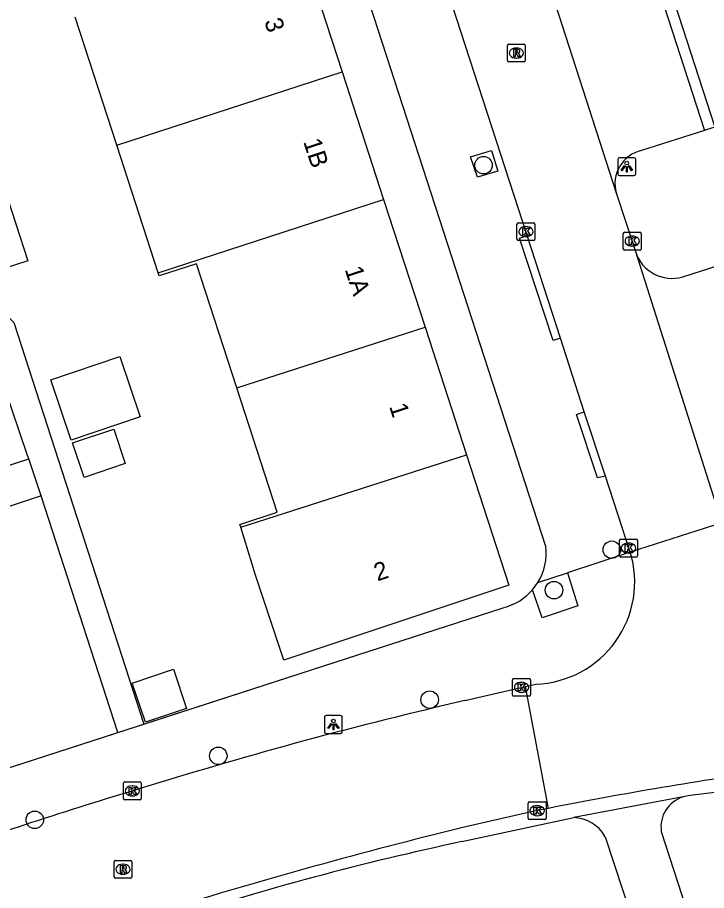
# Model space of a CAD drawing. Extents: x 159265 to 160143, y 383413 to 384319.
# Drawn here: x 159539.86 to 159578.35, y 383875.38 to 383924.16 of the extents above; entities that cross this region are included whole.
import ezdxf

# ---------------------------------------------------------------- set-up
doc = ezdxf.new("R2010")
doc.units = 0
for name, color, linetype in [('IMGEO_Boom', 7, 'Continuous'), ('IMGEO_Groenvoorziening', 7, 'Continuous'), ('IMGEO_Kolk', 7, 'Continuous'), ('IMGEO_Lichtpunt', 7, 'Continuous'), ('IMGEO_Muur', 7, 'Continuous'), ('IMGEO_Pand', 7, 'Continuous'), ('IMGEO_Pand_nummerreeks', 7, 'Continuous'), ('IMGEO_Parkeervlak_open', 7, 'Continuous'), ('IMGEO_Rijbaan_lokaal_open', 7, 'Continuous'), ('IMGEO_Rioolput', 7, 'Continuous'), ('IMGEO_Voetpad_open', 7, 'Continuous')]:
    doc.layers.add(name, color=color, linetype=linetype)

msp = doc.modelspace()

# ---------------------------------------------------------------- linework, layer by layer
at = {"layer": 'IMGEO_Boom'}
for centre in [(159565.896, 383915.907), (159573.059, 383894.421), (159569.835, 383892.161), (159562.889, 383886.043), (159551.075, 383882.908), (159540.823, 383879.332)]:
    msp.add_circle(centre, 0.489, dxfattribs=at)
at = {"layer": 'IMGEO_Groenvoorziening'}
msp.add_lwpolyline([(159568.639, 383892.186), (159568.936, 383892.591)], dxfattribs=at)
at = {"layer": 'IMGEO_Kolk'}
for p, q in [((159567.764, 383911.77), (159567.764, 383912.622)), ((159567.839, 383912.696), (159568.691, 383912.696)), ((159568.252, 383912.476), (159568.277, 383912.476)), ((159568.765, 383912.622), (159568.765, 383911.77)), ((159573.702, 383911.24), (159573.702, 383912.092)), ((159573.777, 383912.166), (159574.629, 383912.166)), ((159574.703, 383912.092), (159574.703, 383911.24)), ((159568.691, 383911.696), (159567.839, 383911.696)), ((159568.275, 383911.916), (159568.25, 383911.916)), ((159574.19, 383911.946), (159574.215, 383911.946)), ((159574.629, 383911.166), (159573.777, 383911.166)), ((159574.213, 383911.386), (159574.188, 383911.386)), ((159573.493, 383894.087), (159573.493, 383894.939)), ((159573.568, 383895.013), (159574.42, 383895.013)), ((159574.494, 383894.939), (159574.494, 383894.087)), ((159573.981, 383894.793), (159574.006, 383894.793)), ((159574.42, 383894.013), (159573.568, 383894.013)), ((159574.004, 383894.233), (159573.979, 383894.233)), ((159567.518, 383886.306), (159567.518, 383887.158)), ((159567.593, 383887.232), (159568.445, 383887.232)), ((159568.519, 383887.158), (159568.519, 383886.306)), ((159568.006, 383887.012), (159568.031, 383887.012)), ((159568.445, 383886.232), (159567.593, 383886.232)), ((159568.029, 383886.452), (159568.004, 383886.452)), ((159545.774, 383880.517), (159545.774, 383881.369)), ((159545.849, 383881.443), (159546.701, 383881.443)), ((159546.775, 383881.369), (159546.775, 383880.517)), ((159546.262, 383881.223), (159546.287, 383881.223)), ((159546.701, 383880.443), (159545.849, 383880.443)), ((159546.285, 383880.663), (159546.26, 383880.663)), ((159568.466, 383880.34), (159569.318, 383880.34)), ((159568.391, 383879.414), (159568.391, 383880.266)), ((159568.879, 383880.12), (159568.904, 383880.12)), ((159569.392, 383880.266), (159569.392, 383879.414)), ((159569.318, 383879.34), (159568.466, 383879.34)), ((159568.902, 383879.56), (159568.877, 383879.56))]:
    msp.add_line(p, q, dxfattribs=at)
for points in [[(159567.764, 383911.77), (159567.764, 383912.622)], [(159567.839, 383912.696), (159568.691, 383912.696)], [(159568.765, 383912.622), (159568.765, 383911.77)], [(159568.085, 383912.396), (159568.208, 383912.396), (159568.208, 383912.245), (159568.338, 383912.396), (159568.502, 383912.396), (159568.356, 383912.245), (159568.509, 383911.996), (159568.357, 383911.996), (159568.272, 383912.16), (159568.208, 383912.093), (159568.208, 383911.996), (159568.085, 383911.996), (159568.085, 383912.396)], [(159573.702, 383911.24), (159573.702, 383912.092)], [(159573.777, 383912.166), (159574.629, 383912.166)], [(159574.703, 383912.092), (159574.703, 383911.24)], [(159568.691, 383911.696), (159567.839, 383911.696)], [(159574.023, 383911.866), (159574.146, 383911.866), (159574.146, 383911.715), (159574.276, 383911.866), (159574.44, 383911.866), (159574.294, 383911.715), (159574.447, 383911.466), (159574.295, 383911.466), (159574.21, 383911.63), (159574.146, 383911.563), (159574.146, 383911.466), (159574.023, 383911.466), (159574.023, 383911.866)], [(159574.629, 383911.166), (159573.777, 383911.166)], [(159573.493, 383894.087), (159573.493, 383894.939)], [(159573.568, 383895.013), (159574.42, 383895.013)], [(159574.494, 383894.939), (159574.494, 383894.087)], [(159573.814, 383894.713), (159573.937, 383894.713), (159573.937, 383894.562), (159574.067, 383894.713), (159574.231, 383894.713), (159574.085, 383894.562), (159574.238, 383894.313), (159574.086, 383894.313), (159574.001, 383894.477), (159573.937, 383894.41), (159573.937, 383894.313), (159573.814, 383894.313), (159573.814, 383894.713)], [(159574.42, 383894.013), (159573.568, 383894.013)], [(159567.518, 383886.306), (159567.518, 383887.158)], [(159567.593, 383887.232), (159568.445, 383887.232)], [(159568.519, 383887.158), (159568.519, 383886.306)], [(159567.839, 383886.932), (159567.962, 383886.932), (159567.962, 383886.781), (159568.092, 383886.932), (159568.256, 383886.932), (159568.11, 383886.781), (159568.263, 383886.532), (159568.111, 383886.532), (159568.026, 383886.696), (159567.962, 383886.629), (159567.962, 383886.532), (159567.839, 383886.532), (159567.839, 383886.932)], [(159568.445, 383886.232), (159567.593, 383886.232)], [(159545.774, 383880.517), (159545.774, 383881.369)], [(159545.849, 383881.443), (159546.701, 383881.443)], [(159546.775, 383881.369), (159546.775, 383880.517)], [(159546.095, 383881.143), (159546.218, 383881.143), (159546.218, 383880.992), (159546.348, 383881.143), (159546.512, 383881.143), (159546.366, 383880.992), (159546.519, 383880.743), (159546.367, 383880.743), (159546.282, 383880.907), (159546.218, 383880.84), (159546.218, 383880.743), (159546.095, 383880.743), (159546.095, 383881.143)], [(159546.701, 383880.443), (159545.849, 383880.443)], [(159568.466, 383880.34), (159569.318, 383880.34)], [(159568.391, 383879.414), (159568.391, 383880.266)], [(159568.712, 383880.04), (159568.835, 383880.04), (159568.835, 383879.889), (159568.965, 383880.04), (159569.129, 383880.04), (159568.983, 383879.889), (159569.136, 383879.64), (159568.984, 383879.64), (159568.899, 383879.804), (159568.835, 383879.737), (159568.835, 383879.64), (159568.712, 383879.64), (159568.712, 383880.04)], [(159569.392, 383880.266), (159569.392, 383879.414)], [(159569.318, 383879.34), (159568.466, 383879.34)]]:
    msp.add_lwpolyline(points, dxfattribs=at)
for centre, start, end in [((159567.841, 383912.62), 91.552, 178.448), ((159567.841, 383912.62), 91.552, 178.448), ((159568.689, 383912.62), 1.552, 88.448), ((159568.689, 383912.62), 1.552, 88.448), ((159573.779, 383912.09), 91.552, 178.448), ((159573.779, 383912.09), 91.552, 178.448), ((159574.627, 383912.09), 1.552, 88.448), ((159574.627, 383912.09), 1.552, 88.448), ((159567.841, 383911.772), 181.552, 268.448), ((159567.841, 383911.772), 181.552, 268.448), ((159568.689, 383911.772), 271.552, 358.448), ((159568.689, 383911.772), 271.552, 358.448), ((159573.779, 383911.242), 181.552, 268.448), ((159573.779, 383911.242), 181.552, 268.448), ((159574.627, 383911.242), 271.552, 358.448), ((159574.627, 383911.242), 271.552, 358.448), ((159573.57, 383894.937), 91.552, 178.448), ((159573.57, 383894.937), 91.552, 178.448), ((159574.418, 383894.937), 1.552, 88.448), ((159574.418, 383894.937), 1.552, 88.448), ((159573.57, 383894.089), 181.552, 268.448), ((159573.57, 383894.089), 181.552, 268.448), ((159574.418, 383894.089), 271.552, 358.448), ((159574.418, 383894.089), 271.552, 358.448), ((159567.595, 383887.156), 91.552, 178.448), ((159567.595, 383887.156), 91.552, 178.448), ((159568.443, 383887.156), 1.552, 88.448), ((159568.443, 383887.156), 1.552, 88.448), ((159567.595, 383886.308), 181.552, 268.448), ((159567.595, 383886.308), 181.552, 268.448), ((159568.443, 383886.308), 271.552, 358.448), ((159568.443, 383886.308), 271.552, 358.448), ((159545.851, 383881.367), 91.552, 178.448), ((159545.851, 383881.367), 91.552, 178.448), ((159546.699, 383881.367), 1.552, 88.448), ((159546.699, 383881.367), 1.552, 88.448), ((159545.851, 383880.519), 181.552, 268.448), ((159545.851, 383880.519), 181.552, 268.448), ((159546.699, 383880.519), 271.552, 358.448), ((159546.699, 383880.519), 271.552, 358.448), ((159568.468, 383880.264), 91.552, 178.448), ((159568.468, 383880.264), 91.552, 178.448), ((159569.316, 383880.264), 1.552, 88.448), ((159569.316, 383880.264), 1.552, 88.448), ((159568.468, 383879.416), 181.552, 268.448), ((159568.468, 383879.416), 181.552, 268.448), ((159569.316, 383879.416), 271.552, 358.448), ((159569.316, 383879.416), 271.552, 358.448)]:
    msp.add_arc(centre, 0.0765, start, end, dxfattribs=at)
for centre, major_axis, ratio, start_param, end_param in [((159568.251, 383912.196), (-0.387, 0.002), 0.722429, 4.712389, 7.853982), ((159568.276, 383912.196), (-0.39, 0.002), 0.717154, 1.570796, 4.712389), ((159574.189, 383911.666), (-0.387, 0.002), 0.722429, 4.712389, 7.853982), ((159574.214, 383911.666), (-0.39, 0.002), 0.717154, 1.570796, 4.712389), ((159573.98, 383894.513), (-0.387, 0.002), 0.722429, 4.712389, 7.853982), ((159574.005, 383894.513), (-0.39, 0.002), 0.717154, 1.570796, 4.712389), ((159568.005, 383886.732), (-0.387, 0.002), 0.722429, 4.712389, 7.853982), ((159568.03, 383886.732), (-0.39, 0.002), 0.717154, 1.570796, 4.712389), ((159546.261, 383880.943), (-0.387, 0.002), 0.722429, 4.712389, 7.853982), ((159546.286, 383880.943), (-0.39, 0.002), 0.717154, 1.570796, 4.712389), ((159568.878, 383879.84), (-0.387, 0.002), 0.722429, 4.712389, 7.853982), ((159568.903, 383879.84), (-0.39, 0.002), 0.717154, 1.570796, 4.712389)]:
    msp.add_ellipse(centre, major_axis=major_axis, ratio=ratio, start_param=start_param, end_param=end_param, dxfattribs=at)
at = {"layer": 'IMGEO_Lichtpunt'}
for p, q in [((159573.399, 383916.228), (159573.399, 383915.421)), ((159573.399, 383916.228), (159573.399, 383915.421)), ((159574.301, 383916.323), (159573.493, 383916.323)), ((159574.301, 383916.323), (159573.493, 383916.323)), ((159574.395, 383915.421), (159574.395, 383916.228)), ((159574.395, 383915.421), (159574.395, 383916.228)), ((159573.493, 383915.327), (159574.301, 383915.327)), ((159573.493, 383915.327), (159574.301, 383915.327)), ((159557.01, 383885.056), (159557.01, 383884.249)), ((159557.01, 383885.056), (159557.01, 383884.249)), ((159557.912, 383885.151), (159557.104, 383885.151)), ((159557.912, 383885.151), (159557.104, 383885.151)), ((159558.006, 383884.249), (159558.006, 383885.056)), ((159558.006, 383884.249), (159558.006, 383885.056)), ((159557.104, 383884.155), (159557.912, 383884.155)), ((159557.104, 383884.155), (159557.912, 383884.155))]:
    msp.add_line(p, q, dxfattribs=at)
for points in [[(159573.773, 383915.892), (159573.812, 383915.864), (159573.624, 383915.602), (159573.586, 383915.629), (159573.773, 383915.892)], [(159573.985, 383915.864), (159574.023, 383915.891), (159574.21, 383915.629), (159574.171, 383915.601), (159573.985, 383915.864)], [(159573.875, 383915.844), (159573.922, 383915.844), (159573.922, 383915.522), (159573.875, 383915.522), (159573.875, 383915.844)], [(159557.384, 383884.72), (159557.423, 383884.692), (159557.235, 383884.43), (159557.197, 383884.457), (159557.384, 383884.72)], [(159557.486, 383884.672), (159557.533, 383884.672), (159557.533, 383884.35), (159557.486, 383884.35), (159557.486, 383884.672)], [(159557.596, 383884.692), (159557.634, 383884.719), (159557.821, 383884.457), (159557.782, 383884.429), (159557.596, 383884.692)]]:
    msp.add_lwpolyline(points, dxfattribs=at)
for centre in [(159573.898, 383916.026), (159557.509, 383884.854)]:
    msp.add_circle(centre, 0.0994, dxfattribs=at)
for centre, start, end in [((159573.493, 383916.228), 90, 180), ((159573.493, 383916.228), 90, 180), ((159574.301, 383916.228), 0, 90), ((159574.301, 383916.228), 0, 90), ((159573.493, 383915.421), 180, 270), ((159573.493, 383915.421), 180, 270), ((159574.301, 383915.421), 270, 0), ((159574.301, 383915.421), 270, 360), ((159557.104, 383885.056), 90, 180), ((159557.104, 383885.056), 90, 180), ((159557.912, 383885.056), 0, 90), ((159557.912, 383885.056), 0, 90), ((159557.104, 383884.249), 180, 270), ((159557.104, 383884.249), 180, 270), ((159557.912, 383884.249), 270, 0), ((159557.912, 383884.249), 270, 360)]:
    msp.add_arc(centre, 0.0946, start, end, dxfattribs=at)
at = {"layer": 'IMGEO_Muur'}
msp.add_lwpolyline([(159533.665, 383880.391), (159557.611, 383888.144)], dxfattribs=at)
at = {"layer": 'IMGEO_Pand'}
for points in [[(159555.678, 383928.279), (159558, 383921.124)], [(159545.401, 383917.028), (159543.08, 383924.181)], [(159545.401, 383917.028), (159558, 383921.124)], [(159558, 383921.124), (159560.313, 383913.997)], [(159547.717, 383909.894), (159545.401, 383917.028)], [(159536.668, 383913.918), (159539.099, 383914.705), (159540.438, 383910.566), (159538.007, 383909.78), (159536.668, 383913.918)], [(159547.717, 383909.894), (159560.313, 383913.997)], [(159560.313, 383913.997), (159562.629, 383906.861)], [(159552.113, 383903.466), (159549.862, 383910.402), (159547.772, 383909.723), (159547.717, 383909.894)], [(159552.113, 383903.466), (159562.629, 383906.861)], [(159562.629, 383906.861), (159564.943, 383899.731)], [(159545.576, 383905.211), (159546.709, 383901.848), (159542.856, 383900.549), (159541.722, 383903.911), (159545.576, 383905.211)], [(159552.327, 383895.676), (159552.277, 383895.839), (159554.368, 383896.518), (159552.113, 383903.466)], [(159545.234, 383901.166), (159545.883, 383899.24), (159543.588, 383898.466), (159542.939, 383900.392), (159545.234, 383901.166)], [(159541.181, 383897.44), (159538.261, 383896.456), (159537.556, 383898.547), (159540.487, 383899.497)], [(159541.181, 383897.44), (159540.487, 383899.497)], [(159564.943, 383899.731), (159567.309, 383892.44), (159554.741, 383888.248), (159553.159, 383892.991), (159552.327, 383895.676)], [(159552.327, 383895.676), (159564.943, 383899.731)], [(159548.579, 383887.742), (159549.309, 383885.552), (159547.003, 383884.782), (159546.273, 383886.973), (159548.579, 383887.742)]]:
    msp.add_lwpolyline(points, dxfattribs=at)
at = {"layer": 'IMGEO_Parkeervlak_open'}
msp.add_lwpolyline([(159574.853, 383928.319), (159578.244, 383917.849)], dxfattribs=at)
at = {"layer": 'IMGEO_Rijbaan_lokaal_open'}
for points in [[(159560.334, 383954.623), (159573.312, 383914.357)], [(159568.333, 383911.982), (159560.937, 383934.748)], [(159573.312, 383914.357), (159574.378, 383911.079)], [(159570.194, 383906.241), (159568.333, 383911.982)], [(159574.378, 383911.079), (159578.987, 383896.617), (159579.2, 383895.932)], [(159571.525, 383902.126), (159570.194, 383906.241)], [(159572.705, 383898.533), (159571.525, 383902.126)], [(159574.089, 383894.293), (159572.705, 383898.533)], [(159579.2, 383895.932), (159574.089, 383894.293)], [(159564.857, 383885.994), (159568.238, 383886.779)], [(159568.238, 383886.779), (159568.811, 383886.912)], [(159569.525, 383879.968), (159568.238, 383886.779)], [(159569.525, 383879.968), (159568.893, 383879.841), (159564.739, 383878.897)]]:
    msp.add_lwpolyline(points, dxfattribs=at)
for centre, radius, start, end in [((159568.629, 383892.62), 5.711, 271.8289, 17.0356), ((159620.157, 383646.422), 245.871, 102.99785, 107.29026), ((159610.494, 383674.877), 209.143, 97.76539, 101.29666), ((159611.747, 383663.024), 227.542, 106.51077, 109.70485), ((159634.073, 383596.075), 291.196, 103.77455, 107.17535)]:
    msp.add_arc(centre, radius, start, end, dxfattribs=at)
at = {"layer": 'IMGEO_Rioolput'}
for p, q in [((159567.228, 383921.75), (159567.228, 383922.602)), ((159567.303, 383922.676), (159568.155, 383922.676)), ((159567.716, 383922.456), (159567.741, 383922.456)), ((159568.229, 383922.602), (159568.229, 383921.75)), ((159567.739, 383921.896), (159567.714, 383921.896)), ((159568.155, 383921.676), (159567.303, 383921.676)), ((159545.251, 383876.138), (159545.251, 383876.99)), ((159545.326, 383877.064), (159546.178, 383877.064)), ((159546.252, 383876.99), (159546.252, 383876.138)), ((159545.739, 383876.844), (159545.764, 383876.844)), ((159546.178, 383876.064), (159545.326, 383876.064)), ((159545.762, 383876.284), (159545.737, 383876.284))]:
    msp.add_line(p, q, dxfattribs=at)
for points in [[(159567.228, 383921.75), (159567.228, 383922.602)], [(159567.303, 383922.676), (159568.155, 383922.676)], [(159567.817, 383922.374), (159567.565, 383922.376), (159567.565, 383921.976)], [(159567.743, 383922.295), (159567.689, 383922.295), (159567.689, 383922.214)], [(159568.229, 383922.602), (159568.229, 383921.75)], [(159567.565, 383921.976), (159567.689, 383921.976), (159567.689, 383922.138), (159567.7, 383922.138)], [(159567.689, 383922.214), (159567.741, 383922.214)], [(159567.747, 383922.109), (159567.818, 383921.976), (159567.958, 383921.976), (159567.893, 383922.102)], [(159568.155, 383921.676), (159567.303, 383921.676)], [(159545.251, 383876.138), (159545.251, 383876.99)], [(159545.326, 383877.064), (159546.178, 383877.064)], [(159546.252, 383876.99), (159546.252, 383876.138)], [(159545.84, 383876.762), (159545.588, 383876.764), (159545.588, 383876.364)], [(159545.588, 383876.364), (159545.712, 383876.364), (159545.712, 383876.526), (159545.723, 383876.526)], [(159545.766, 383876.683), (159545.712, 383876.683), (159545.712, 383876.602)], [(159545.712, 383876.602), (159545.764, 383876.602)], [(159545.77, 383876.497), (159545.841, 383876.364), (159545.981, 383876.364), (159545.916, 383876.49)], [(159546.178, 383876.064), (159545.326, 383876.064)]]:
    msp.add_lwpolyline(points, dxfattribs=at)
for centre, radius, start, end in [((159567.305, 383922.6), 0.0765, 91.552, 178.448), ((159567.305, 383922.6), 0.0765, 91.552, 178.448), ((159567.749, 383922.199), 0.0964, 77.0061, 93.1865), ((159567.763, 383922.256), 0.0378, 276.6634, 79.6772), ((159567.816, 383922.264), 0.109, 350.3612, 89.416), ((159567.814, 383922.264), 0.112, 277.5842, 350.9817), ((159568.153, 383922.6), 0.0765, 1.552, 88.448), ((159568.153, 383922.6), 0.0765, 1.552, 88.448), ((159567.305, 383921.752), 0.0765, 181.552, 268.448), ((159567.305, 383921.752), 0.0765, 181.552, 268.448), ((159567.699, 383922.085), 0.0533, 26.0293, 88.6989), ((159567.725, 383922.403), 0.19, 274.7715, 282.9687), ((159567.798, 383922.049), 0.108, 29.5134, 73.7905), ((159568.153, 383921.752), 0.0765, 271.552, 358.448), ((159568.153, 383921.752), 0.0765, 271.552, 358.448), ((159545.328, 383876.988), 0.0765, 91.552, 178.448), ((159545.328, 383876.988), 0.0765, 91.552, 178.448), ((159546.176, 383876.988), 0.0765, 1.552, 88.448), ((159546.176, 383876.988), 0.0765, 1.552, 88.448), ((159545.722, 383876.473), 0.0533, 26.0293, 88.6989), ((159545.748, 383876.791), 0.19, 274.7715, 282.9687), ((159545.772, 383876.587), 0.0964, 77.0061, 93.1865), ((159545.786, 383876.644), 0.0378, 276.6634, 79.6772), ((159545.839, 383876.652), 0.109, 350.3612, 89.416), ((159545.837, 383876.652), 0.112, 277.5842, 350.9817), ((159545.821, 383876.437), 0.108, 29.5134, 73.7905), ((159545.328, 383876.14), 0.0765, 181.552, 268.448), ((159545.328, 383876.14), 0.0765, 181.552, 268.448), ((159546.176, 383876.14), 0.0765, 271.552, 358.448), ((159546.176, 383876.14), 0.0765, 271.552, 358.448)]:
    msp.add_arc(centre, radius, start, end, dxfattribs=at)
for centre, major_axis, ratio, start_param, end_param in [((159567.715, 383922.176), (-0.387, 0.002), 0.722429, 4.712389, 7.853982), ((159567.74, 383922.176), (-0.39, 0.002), 0.717154, 1.570796, 4.712389), ((159545.738, 383876.564), (-0.387, 0.002), 0.722429, 4.712389, 7.853982), ((159545.763, 383876.564), (-0.39, 0.002), 0.717154, 1.570796, 4.712389)]:
    msp.add_ellipse(centre, major_axis=major_axis, ratio=ratio, start_param=start_param, end_param=end_param, dxfattribs=at)
at = {"layer": 'IMGEO_Voetpad_open'}
for points in [[(159569.381, 383894.609), (159551.776, 383948.854)], [(159575.424, 383928.511), (159578.819, 383918.035), (159578.584, 383917.959), (159578.244, 383917.849)], [(159578.244, 383917.849), (159574.725, 383916.727)], [(159566.34, 383916.724), (159566.69, 383915.572), (159565.552, 383915.234), (159565.171, 383916.383), (159566.34, 383916.724)], [(159570.194, 383906.241), (159569.78, 383906.108), (159567.907, 383911.836), (159568.333, 383911.982)], [(159577.023, 383909.665), (159580.566, 383910.801)], [(159540.487, 383899.497), (159540.426, 383899.679), (159539.55, 383902.277), (159538.026, 383906.798), (159538.442, 383908.353), (159539.648, 383907.11), (159546.91, 383884.679)], [(159572.705, 383898.533), (159572.265, 383898.438), (159571.096, 383901.978), (159571.525, 383902.126)], [(159545.464, 383884.211), (159541.181, 383897.44)], [(159574.089, 383894.293), (159570.586, 383893.133)], [(159570.586, 383893.133), (159571.165, 383891.284), (159569.172, 383890.612), (159568.639, 383892.186)], [(159568.936, 383892.591), (159570.586, 383893.133)], [(159546.91, 383884.679), (159557.611, 383888.144), (159566.997, 383891.183)], [(159545.464, 383884.211), (159546.91, 383884.679)], [(159524.454, 383877.425), (159533.665, 383880.391), (159545.464, 383884.211)], [(159609.082, 383884.518), (159577.432, 383880.683)], [(159577.04, 383880.609), (159570.936, 383879.456)], [(159564.691, 383878.113), (159570.936, 383879.456)], [(159572.699, 383878.387), (159575.14, 383870.916)], [(159575.826, 383878.684), (159578.153, 383871.502)]]:
    msp.add_lwpolyline(points, dxfattribs=at)
for centre, radius, start, end in [((159575.129, 383914.88), 1.891, 102.3445, 196.0485), ((159576.435, 383911.745), 2.162, 197.9526, 285.79), ((159566.26, 383894.239), 3.143, 328.3727, 6.7561), ((159566.258, 383894.238), 3.143, 283.5964, 319.2401), ((159577.56, 383878.936), 1.752, 107.2702, 188.2547), ((159577.565, 383878.903), 1.785, 94.2739, 107.1065), ((159570.856, 383877.335), 2.122, 29.7077, 87.831), ((159599.285, 383716.228), 165.54, 102.0625, 107.94163)]:
    msp.add_arc(centre, radius, start, end, dxfattribs=at)

# ---------------------------------------------------------------- texts
at = {"layer": 'IMGEO_Pand_nummerreeks'}
for s, rotation, p in [('3', 287.9798, (159553.634, 383923.952)), ('1B', 287.9799, (159555.816, 383917.227)), ('1A', 287.9798, (159558.131, 383910.095)), ('1', 287.9799, (159560.615, 383902.437)), ('2', 18.4459, (159559.964, 383892.647))]:
    msp.add_text(s, height=1, rotation=rotation, dxfattribs=at).set_placement(p)

doc.saveas('drawing.dxf')
